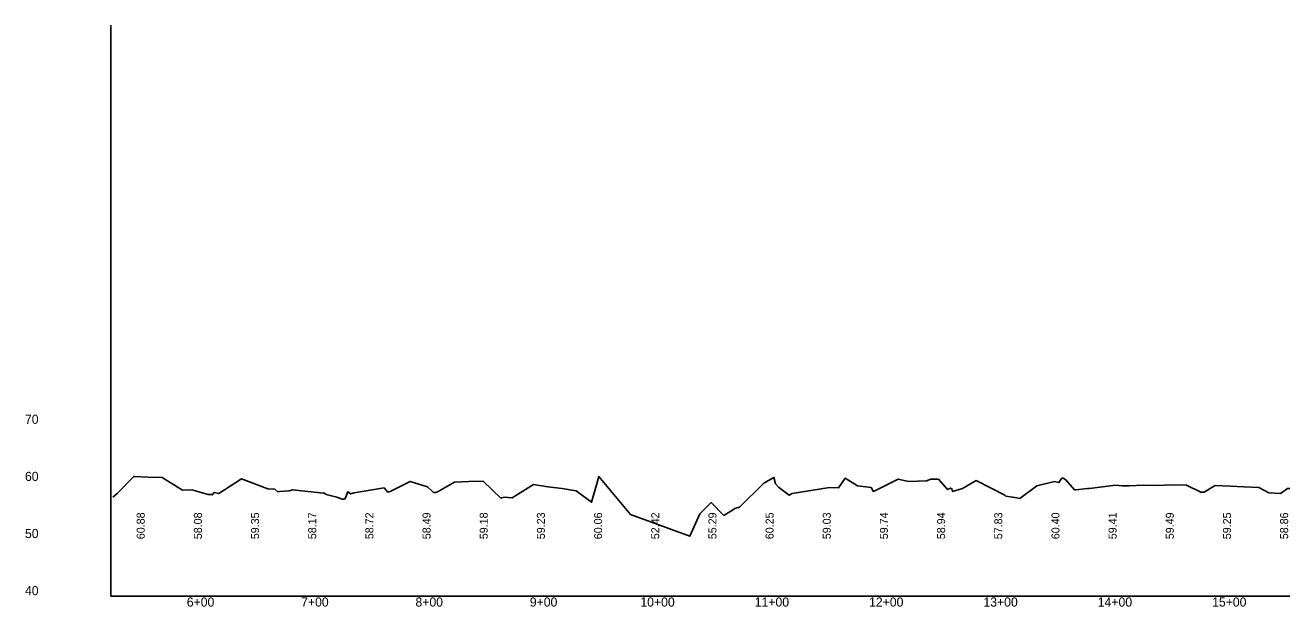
# Model space of a CAD drawing. Extents: x 2526761 to 2530854, y 882903 to 888012.
# Drawn here: x 2526764 to 2527870, y 882903 to 883412 of the extents above; entities that cross this region are included whole.
import ezdxf

# ---------------------------------------------------------------- set-up
doc = ezdxf.new("R2010")
doc.units = 0
for name, color, linetype in [('RD_DDB_ElevTX', 7, 'Continuous'), ('RD_DDB_Profile_EX', 7, 'Continuous'), ('RD_DDB_StaTX', 7, 'Continuous'), ('RD_DDB_StripGrade', 7, 'Continuous'), ('RD_GPK_Profile_Cell', 7, 'Continuous')]:
    doc.layers.add(name, color=color, linetype=linetype)

msp = doc.modelspace()

# ---------------------------------------------------------------- linework, layer by layer
at = {"layer": 'RD_DDB_Profile_EX'}
for points in [[(2526840.8, 882999), (2526844.5, 883002.2), (2526859, 883017.1), (2526871.5, 883016.4), (2526884, 883016.2), (2526901.8, 883005.1), (2526909.9, 883005.4), (2526924, 883001.2), (2526927.2, 883001.3), (2526927.7, 883000.9), (2526929.3, 883003.1), (2526933.4, 883002), (2526953.4, 883015), (2526976.4, 883006.3), (2526982.5, 883005.8), (2526984.9, 883003.6), (2526986.4, 883003.8), (2526994.9, 883004.4), (2526998.1, 883005.4), (2527024.8, 883002.3), (2527025.8, 883002.5), (2527027.4, 883001.1), (2527036.6, 882998.8), (2527041.2, 882997.3), (2527042.9, 882997.3), (2527044, 882997.6), (2527046.2, 883003.7), (2527048.6, 883001.7), (2527051.7, 883002.8), (2527078, 883007), (2527081.2, 883003.3), (2527083.3, 883003.8), (2527100.8, 883012.7), (2527115.8, 883007.9), (2527120.4, 883003.9), (2527121.3, 883003.1), (2527123.3, 883002.9), (2527125.2, 883003.8), (2527139.5, 883012.1), (2527152, 883012.7), (2527164.5, 883012.9), (2527180.1, 882998.1), (2527180.7, 882998.2), (2527182.2, 882998.7), (2527183.4, 882998.9), (2527190.1, 882998.2), (2527208.7, 883009.9), (2527221.1, 883008), (2527233.7, 883006.4), (2527246, 883004.5), (2527259.4, 882994.4), (2527264.4, 883011.7), (2527265.9, 883016.9), (2527291.9, 882985.4), (2527293.6, 882983.8), (2527345.4, 882964.7), (2527354.2, 882984.3), (2527364.1, 882994.1), (2527375.1, 882983), (2527383.5, 882988), (2527384.7, 882989.1), (2527388.7, 882990.1), (2527410.2, 883011.1), (2527418.8, 883016.2), (2527420.4, 883010.6), (2527422.8, 883007.7), (2527429.9, 883002.4), (2527432.1, 883000.7), (2527434.8, 883002.2), (2527467.6, 883007.3), (2527475.4, 883007.1), (2527481.1, 883015.5), (2527492.1, 883008.9), (2527503.9, 883007.3), (2527505, 883005.2), (2527505.6, 883003.9), (2527507.6, 883004.7), (2527527.5, 883014.7), (2527536.7, 883012.6), (2527552.4, 883013.1), (2527556.2, 883014.7), (2527562.8, 883014.8), (2527570.7, 883005.5), (2527573.2, 883006.7), (2527574.5, 883006.3), (2527575.1, 883003.8), (2527583.7, 883006.5), (2527595.8, 883013.5), (2527620.7, 883000.7), (2527621.2, 883000.4), (2527621.8, 882999.9), (2527629.7, 882998.6), (2527634, 882997.6), (2527648.8, 883008.8), (2527664.3, 883012.5), (2527668.1, 883011.8), (2527669.8, 883014.3), (2527670.8, 883015.4), (2527671.8, 883015.6), (2527674.2, 883014), (2527681.7, 883005.2)], [(2527681.7, 883005.2), (2527683, 883005.2), (2527693.1, 883006.4), (2527694.9, 883006.4), (2527717.6, 883009.3), (2527723.4, 883008.8), (2527729.6, 883008.9), (2527742, 883009.5), (2527754.7, 883009.2), (2527766.2, 883009.6), (2527779.7, 883009.3), (2527792.1, 883003.3), (2527793.4, 883003.3), (2527795.2, 883003.2), (2527804.7, 883009.2), (2527818.2, 883008.4), (2527829.9, 883008.1), (2527843.1, 883007.4), (2527851.7, 883002.8), (2527862, 883002.1), (2527867.9, 883006.5), (2527868.5, 883006.4), (2527870, 883006.4)]]:
    msp.add_lwpolyline(points, dxfattribs=at)
at = {"layer": 'RD_GPK_Profile_Cell'}
for q in [(2526839, 883412.1), (2527870, 882912.1), (2526839, 882912.1)]:
    msp.add_line((2526839, 882912.1), q, dxfattribs=at)

# ---------------------------------------------------------------- texts
at = {"layer": 'RD_DDB_ElevTX'}
for s, p in [('70', (2526763.9, 883063.1)), ('60', (2526763.9, 883013.1)), ('50', (2526763.9, 882963.1)), ('40', (2526763.9, 882913.1))]:
    msp.add_text(s, height=8, dxfattribs=at).set_placement(p)
at = {"layer": 'RD_DDB_StaTX'}
for s, p in [('6+00', (2526905.4, 882903.1)), ('7+00', (2527005.4, 882903.1)), ('8+00', (2527105.4, 882903.1)), ('9+00', (2527205.4, 882903.1)), ('10+00', (2527302.1, 882903.1)), ('11+00', (2527402.1, 882903.1)), ('12+00', (2527502.1, 882903.1)), ('13+00', (2527602.1, 882903.1)), ('14+00', (2527702.1, 882903.1)), ('15+00', (2527802.1, 882903.1))]:
    msp.add_text(s, height=8, dxfattribs=at).set_placement(p)
at = {"layer": 'RD_DDB_StripGrade'}
for s, p in [('60.88', (2526868.6, 882962.1)), ('58.08', (2526918.6, 882962.1)), ('59.35', (2526968.6, 882962.1)), ('58.17', (2527018.6, 882962.1)), ('58.72', (2527068.6, 882962.1)), ('58.49', (2527118.6, 882962.1)), ('59.18', (2527168.6, 882962.1)), ('59.23', (2527218.6, 882962.1)), ('60.06', (2527268.6, 882962.1)), ('52.42', (2527318.6, 882962.1)), ('55.29', (2527368.6, 882962.1)), ('60.25', (2527418.6, 882962.1)), ('59.03', (2527468.6, 882962.1)), ('59.74', (2527518.6, 882962.1)), ('58.94', (2527568.6, 882962.1)), ('57.83', (2527618.6, 882962.1)), ('60.40', (2527668.6, 882962.1)), ('59.41', (2527718.6, 882962.1)), ('59.49', (2527768.6, 882962.1)), ('59.25', (2527818.6, 882962.1)), ('58.86', (2527868.6, 882962.1))]:
    msp.add_text(s, height=7, rotation=90, dxfattribs=at).set_placement(p)
at = {"layer": 'RD_GPK_Profile_Cell'}
for s, p in [('059', (2526839, 882916.5)), ('BRANCH1', (2526839, 882915.8)), ('519.310000', (2526839, 882915.2)), ('40', (2526839, 882914.6)), ('50', (2526839, 882914)), ('10', (2526839, 882913.3)), ('NOGAP', (2526839, 882912.7))]:
    msp.add_text(s, height=0.208, dxfattribs=at).set_placement(p)

doc.saveas('drawing.dxf')
